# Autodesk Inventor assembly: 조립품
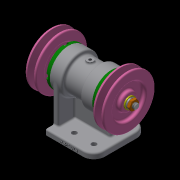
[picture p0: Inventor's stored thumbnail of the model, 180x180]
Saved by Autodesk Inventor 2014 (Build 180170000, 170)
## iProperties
Created: 2020-06
Part Number: 조립품
Document SubType Name: Assembly
Designer: kh
Author: kh
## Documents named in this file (12)
- C:\Users\kh\Desktop\700606V1051\조립품.iam
- C:\Users\kh\Desktop\700606V1051\본체.ipt
- C:\Users\kh\Desktop\700606V1051\베어링 6204.ipt
- C:\Users\kh\Desktop\700606V1051\커버.ipt
- C:\Users\kh\Desktop\700606V1051\오일 실 20 32 5.ipt
- C:\Users\kh\Desktop\700606V1051\축.ipt
- C:\Users\kh\Desktop\700606V1051\키 5x5x12.ipt
- C:\Users\kh\Desktop\700606V1051\V-벨트풀리.ipt
- C:\Users\kh\Desktop\700606V1051\평면 와셔 10x21.ipt
- C:\Users\kh\Desktop\700606V1051\스프링 와셔 10.ipt
- C:\Users\kh\Desktop\700606V1051\너트 M10.ipt
- C:\Users\kh\Desktop\700606V1051\볼트 M4.ipt
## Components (2 placed, 1 different names)
1. V-벨트풀리:1 — Mate:9, Flush:1, Angle:2, Mate:12
2. V-벨트풀리:2 — Mate:10, Flush:2, Angle:3, Mate:18
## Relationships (8: Mate 4, Flush 2, Angle 2)
- Mate:9: V-벨트풀리:1
- Flush:1: V-벨트풀리:1
- Angle:2: V-벨트풀리:1
- Mate:10: V-벨트풀리:2
- Flush:2: V-벨트풀리:2
- Angle:3: V-벨트풀리:2
- Mate:12: V-벨트풀리:1
- Mate:18: V-벨트풀리:2
